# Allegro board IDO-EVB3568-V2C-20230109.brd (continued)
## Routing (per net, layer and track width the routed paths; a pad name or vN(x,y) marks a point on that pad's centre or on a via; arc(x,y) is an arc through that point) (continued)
GND_EARTH: length 49.6
  L3-POW w0.627: 17.43,78.18 J22.SH1 15.98,79.63 ; J23.SH1 36.22,78.18 ; J23.SH1 33.33,78.18 ; J23.SH1 34.78,79.63 ; 30.22,78.18 J22.SH2 ; J22.SH2 33.12,78.18 ; J22.SH2 31.67,79.63 ; 49.02,78.18 J23.SH2 50.47,79.63
  BOTTOM w0.127: HOLE1.1 4.26,74.49
  BOTTOM w1.524: J22.SH1 J22.SH2 J23.SH1 J23.SH2
GND_IN: length 33.4
  TOP w0.127: v1(9.54,65.35) 9.54,66.77 v1(9.8,67.03)
  TOP w0.508: L1.2 10.09,64.31 10.36,64.59 v1(10.36,65.35) ; L1.2 10.05,64.21 9.54,63.7 v1(8.97,63.7) ; L1.2 9.79,64.57 ; v1(8.99,67.03) v1(9.8,67.03) ; v1(9.54,65.35) 9.54,64.82 9.79,64.57 ; 9.79,64.57 v1(8.99,64.57)
  L3-POW w0.627: 3.42,22.96 J30.2 ; J30.2 4.19,22.18 ; J30.2 4.97,22.96 ; J30.2 4.19,23.73 ; J1.2 12.48,81.32 ; J1.2 11.5,79.64 ; J1.2 11.5,82.99 ; J1.2 10.52,81.32 ; 10.01,3 J18.2 10.79,3.78 ; J32.1 11.42,84 ; J32.1 10.65,83.22 ; J32.1 9.87,84 ; J32.1 10.65,84.78 ; 6.3,79.64 J1.3 ; J1.3 5.32,81.32 ; J1.3 6.3,82.99 ; J1.3 7.28,81.32 ; J32.2 8.65,84.78 ; J32.2 7.87,84 ; J32.2 9.42,84 ; J32.2 8.65,83.22 ; 4.19,24.18 J30.1 ; J30.1 4.19,25.73 ; J30.1 3.42,24.96 ; J30.1 4.97,24.96 ; 8.79,3.78 J18.1 9.57,3
  vias: v1(9.3,12.65) v1(9.47,11.76) v1(9.45,11.02) v1(9.86,73.76) v1(9.86,73.05) v1(9.86,12.4) v1(10.06,11.73) v1(10.54,73.76) v1(10.57,73.1) v1(11.18,73.74) v1(11.18,73.08) v1(13.28,8.33) v1(13.84,8.36)
VBAT_RTC: length 82.1
  TOP w0.381: D70.A 75.26,32.21 74.83,31.78 74.83,25.02 v1(77.8,22.05)
  TOP w0.508: J25.1 v1(25.87,5.4) ; v1(69.06,8.71) 69.06,9.8 71.2,11.94 v1(71.2,15.57)
  L2-GND w0.508: v1(69.06,8.71) 69.6,8.18 69.6,3.18 69.42,3 v1(69.42,2.36)
  BOTTOM w0.508: v1(69.42,2.36) 37.03,2.36 34.24,5.16 26.11,5.16 v1(25.87,5.4) ; v1(77.8,22.05) 77.67,22.05 v1(71.2,15.57)
VBAT_WL_1T1R:
  vias: v1(117.04,22.43) v1(117.42,21.92) v1(117.81,22.43) v1(121.97,35.26) v1(121.97,34.62) v1(121.97,33.99)
VBUSM: length 5.7
  TOP w0.254: R74.1 103.4,45.47 103.58,45.29 104.22,45.29 104.76,44.74 U8.35
VCC1V5_DVP: length 46.6
  TOP w0.254: J20.3 45.96,9.69 C100.2
  TOP w0.305: v1(66.62,11.38) 65.02,9.78 J19.3
  TOP w0.381: v1(66.62,11.38) C254.2 ; v1(47.35,10.26) 47.35,10.78 C100.2 ; C107.2 63.01,20.85 62.11,19.95 C108.1 R175.2
  TOP w0.508: U16.5 62.75,21.99 63.2,21.54 C107.2 64.33,20.85 C106.2 64.65,20.84 65.35,20.14 65.35,18.69 65.96,18.08 67.56,18.08 69.16,16.48 69.16,14.05 v1(68.4,13.28)
  BOTTOM w0.508: v1(47.35,10.26) 47.37,10.29 54.41,10.29 54.76,10.64 62.43,10.64 62.89,10.19 65.43,10.19 v1(66.62,11.38) 66.62,11.46 68.4,13.23 v1(68.4,13.28)
VCC1V8_DVP: length 68.7
  TOP w0.254: 43.23,16.38 43.23,15.57 Q17.1 43.24,15.5 42.85,15.11 42.85,14.09 R161.2 ; 43.23,16.38 44.65,16.38 44.83,16.21 v1(45.14,16.21) ; 43.23,16.38 41.38,16.38 41.2,16.21 41.2,15.58 Q16.1 ; v1(45.73,10.28) 45.46,10 J20.4 ; v1(47.04,16.23) 46.45,15.65 R162.2
  TOP w0.305: v1(65.61,11.38) 65.61,11 64.52,9.91 J19.4
  TOP w0.381: C104.2 46.18,10.73 v1(45.73,10.28) ; R166.2 48.74,13.94 v1(49.23,14.43) 49.23,15.85 48.32,16.76 48.31,16.76 48.25,16.82 47.76,16.82 47.17,16.23 v1(47.04,16.23) ; C255.2 v1(65.61,11.38)
  TOP w0.508: v1(67.51,15.95) 67.77,15.7 R156.2 ; U15.5 57.63,21.69 57.25,21.31 C103.2 ; C103.2 57.26,20.84 C102.2 58.81,20.84 59.23,20.42 59.23,18.9 58.88,18.54 v1(58.88,17.98) 58.37,17.48 53.95,17.48 52.07,15.6 52.07,15.16 51.32,14.41 50.76,14.41 v1(50.75,14.43) 50.75,14.17 49.1,12.52 49.1,9.09 v1(49.23,8.97) ; C103.2 56.91,20.85 56.59,20.52 56.59,20.4 56.14,19.95 R172.2
  BOTTOM w0.381: v1(50.75,14.43) v1(49.23,14.43) ; v1(47.04,16.23) 46.86,16.05 45.29,16.05 v1(45.14,16.21)
  BOTTOM w0.508: v1(49.23,8.97) 47.35,8.97 46.03,10.28 v1(45.73,10.28) ; 64.97,13.92 64.97,12.01 v1(65.61,11.38) ; 64.97,13.92 66.12,15.06 66.62,15.06 v1(67.51,15.95) ; 64.97,13.92 63.83,15.06 60.4,15.06 59.51,15.95 59.51,17.35 v1(58.88,17.98)
VCC2V8_DVP: length 36.6
  TOP w0.381: C111.2 68.27,20.72 67.42,19.87 R177.2
  TOP w0.508: C253.2 68.25,11.95 68.28,11.97 v1(68.28,12) 69.8,13.52 69.8,18.11 70.43,18.75 70.43,20.02 69.73,20.72 C110.2 68.41,20.72 C111.2 68.4,21.41 68.28,21.54 U17.5
  BOTTOM w0.508: v1(68.28,12) 65.83,9.55 62.61,9.55 62.03,8.97 55.27,8.97 54.61,9.63 v1(48.34,9.63)
VCC3V3_PHY0: length 33.7
  TOP w0.203: U19.29 36.15,35.89 35.89,35.63 35.89,35.45
  TOP w0.254: C149.2 39.57,43.07 38.87,43.07 37.82,42.01 U19.40
  TOP w0.381: C152.2 37.22,35.45 37.67,35 v1(37.67,34.75) ; C152.2 C151.2 35.89,35.45 ; C152.2 36.91,35.89 v1(36.78,36.02) ; C149.2 39.89,44.33 40.34,44.78 R211.2 v1(40.65,44.2) ; C148.2 28.09,43.51 R258.2 28.19,44.5 29.3,44.5 29.67,44.13 29.67,43.97 30.07,43.57 30.12,43.57 C150.2 ; v1(38.56,36.7) 38.7,36.56 39.72,36.56 40.15,37 R226.2 ; R230.2 44.15,36.71 v1(43.94,36.5)
  BOTTOM w0.381: v1(40.65,44.2) 41.22,44.78 45.16,44.78 45.54,44.4 45.54,40.72 45.16,40.34 45.16,38.68 44.58,38.1 44.58,37.13 v1(43.94,36.5) ; v1(38.56,36.7) 38.56,35.64 v1(37.67,34.75)
  vias: v1(30.68,42.93) v1(30.68,42.37)
VCC3V3_PHY1: length 44.5
  TOP w0.254: U20.40 62.84,41.88 63.42,42.47 63.8,42.47 64.85,43.51 64.85,43.87 ; U20.29 61.42,36.96 60.81,36.35 v1(60.81,36.02) ; U20.11 57.2,41.88 v1(56.21,42.88)
  TOP w0.381: 64.85,43.87 64.47,43.87 v1(63.56,42.96) ; R278.2 R274.2 68.09,34.09 68.43,33.76 R306.2 ; C174.2 55.78,43.31 v1(56.21,42.88)
  TOP w0.508: C173.2 64.85,44.28 64.85,43.87 ; v1(67.01,34.87) 67.01,33.67 C172.2 67.41,33.32 R306.2 ; v1(62.81,35.61) C176.1 C175.2 61.87,35.51 61.37,36.02 v1(60.81,36.02)
  BOTTOM w0.508: v1(60.81,36.02) 57.1,36.02 54.31,38.81 54.31,41.22 55.96,42.88 v1(56.21,42.88) 56.3,42.96 v1(63.56,42.96) ; v1(62.81,35.61) 63.55,34.87 v1(67.01,34.87)
VCC3V3_SD: length 114.9
  TOP w0.254: J2.210 31.92,52.05
  TOP w0.381: J3.4 105.1,74.75 103.45,73.1 D2.2 104.69,72.57 C31.2 105.3,71.96 v1(105.49,71.96) ; v1(41,45.85) 40.44,46.41 39.73,46.41 38.81,47.32 37.03,47.32 35.36,49 34.06,49 33.58,49.48 32.3,49.48 31.92,49.86 31.92,52.05
  BOTTOM w0.381: v1(105.49,71.96) 106.38,71.96 107.14,71.2 107.14,69.93 107.9,69.16 107.9,68.53 106.63,67.26 101.09,67.26 100.97,67.13 98.04,67.13 97.28,66.37 95.25,66.37 94.21,65.33 84.43,65.33 82.63,67.13 70.76,67.13 70.21,66.57 69.62,66.57 65.74,62.69 65.74,53.29 66.47,52.55 66.47,47.5 64.52,45.54 55.76,45.54 53.68,47.62 52.48,47.62 52.27,47.63 51.95,47.63 50.12,45.8 42.98,45.8 42.54,46.24 41.84,46.24 41.45,45.85 v1(41,45.85)
VCC5V0_M:
  vias: v1(21.72,63.07) v1(21.74,63.83) v1(22.35,63.07) v1(22.94,63.07) v1(23.19,63.83) v1(23.57,63.07) v1(24.21,63.07)
VCC5V0_USB1: length 1.3
  TOP w1.016: J7.1 121.72,3.89 122,4.17
  vias: v1(119.08,19.13) v1(119.84,19.13) v1(124.56,14.17) v1(124.56,13.54)
VCC5V0_USB2: length 1.6
  TOP w0.635: 109.93,3 J8.1 110.71,3.78
VCC5V0_USB3: length 1.6
  TOP w0.635: 98.91,3 J9.1 99.69,3.78
VCC5V0_USB_HOST1: length 3.7
  TOP w0.635: 90.67,77.27 J6.10 89.94,78
  BOTTOM w0.635: J6.10 90.67,77.27 ; J6.10 89.2,77.27 ; J6.10 89.94,78
  vias: v1(91.11,73.71) v1(91.59,74.09)
VCC5V0_USB_HOST2: length 1.7
  TOP w1.016: J6.1 91.54,80.47 91.59,80.42
VCC5V0_USB_OTG0: length 1.2
  TOP w0.203: R27.1 123.9,82.01 D7.2
  vias: v1(119.1,56.06) v1(119.74,55.96) v1(123.77,82.88) v1(124.36,82.88) v1(127.63,71.04) v1(128.19,70.64) v1(130.76,82.75) v1(131.39,82.75)
VCC5V_HDMI_TX: length 11
  TOP w0.305: J14.18 67.25,82.11 67.51,82.37 68.15,82.37 68.53,81.99 68.53,80.62 69.88,79.27 71.2,79.27 72.19,78.28 C85.2 72.86,78.62 72.9,78.62 73.07,78.79 D43.C
VCC5V_SPK: length 17.6
  TOP w0.508: 118.95,69.29 119.84,69.29 120.09,69.55 121.17,69.55 C249.2 C252.2 120.97,67.44 120.2,67.44 ; R86.2 109.37,69.61 C250.2 C251.2 111.14,69.29 U11.4 114,69.29 v1(114.38,68.91)
  BOTTOM w0.508: 118.77,68.91 v1(114.38,68.91)
  vias: v1(113.87,68.91) v1(120.32,67.64) v1(120.32,67.03)
VCC5V_SYS: length 55.6
  TOP w0.254: Q5.1 68.76,74.96 v1(68.76,75.06)
  TOP w0.381: C8.2 R4.2 72.85,69.39 73.13,69.67 v1(73.13,70.03) ; 73.61,75.01 D43.A 73.61,76.56 74.88,77.83 74.88,79.6 74.35,80.14 73.48,80.14 71.83,81.79 71.83,83.26 71.45,83.64 57.73,83.64 57.29,84.09 54.62,84.09 ; 73.61,75.01 D42.A 74.22,74.73 74.92,74.02 75.26,74.02 R7.2 ; 73.61,75.01 73.54,75.08 v1(73.13,75.08)
  L2-GND w0.381: v1(60.32,66.5) 61.8,65.02 65.18,65.02 68.66,68.5 71.93,68.5 73.13,69.7 v1(73.13,70.03)
  BOTTOM w0.203: v1(68.76,75.06) 69.77,75.06 70.33,75.62 72.82,75.62 73.13,75.31 v1(73.13,75.08)
  vias: v1(19.18,65.56) v1(19.45,64.96) v1(19.9,65.46) v1(20.04,64.63) v1(22.86,85.93) v1(23.34,85.45) v1(23.79,85.96) v1(24.08,85.45) v1(24.46,85.9) v1(24.71,85.37) v1(54.43,76.3) v1(54.8,75.84) v1(55.12,76.33) v1(55.48,76.9) v1(55.47,75.84) v1(58.27,66.47) v1(59,67.13) v1(59,66.5) v1(59.72,67.13) v1(59.72,66.5) v1(60.4,67.13)
VCC12V_DCIN: length 49.1
  TOP w0.635: J32.4 5.42,84 ; J32.4 4.65,84.78 ; J32.4 3.87,84 ; J32.4 4.65,83.22 ; J18.5 16.79,3.78 ; J18.5 16.79,2.22 ; J18.5 16.01,3 ; J18.5 17.57,3 ; 8.08,14.23 J29.1 ; J29.1 7.25,15.06 ; J29.1 8.91,15.06 ; 2.9,79.64 J1.4 ; J1.4 1.92,81.32 ; J1.4 2.9,82.99 ; J1.4 3.88,81.32 ; J17.1 20.46,6.81 ; J17.1 19.63,5.98 ; J17.1 19.63,7.64 ; 4.19,16.18 J30.5 3.42,16.96 ; 3.42,14.96 J30.6 ; J30.6 4.19,15.73 ; J30.6 4.97,14.96 ; J30.6 4.19,14.18 ; 5.87,84 J32.3 ; J32.3 6.65,84.78 ; J32.3 7.42,84 ; J18.6 18.79,3.78 ; J18.6 18.79,2.22 ; J18.6 19.57,3 ; J18.6 18.01,3
  TOP w2.032: F2.1 16.26,72.11 16.21,72.16
  L2-GND w0.627: J29.1 8.08,15.74 ; J29.1 7.4,15.06 ; J29.1 8.08,14.38 ; 18.79,2.22 J18.6 ; J18.6 19.57,3 ; J18.6 18.79,3.78 ; J18.6 18.01,3 ; J18.5 17.57,3 ; J18.5 16.01,3 ; J18.5 16.79,2.22 ; J18.5 16.79,3.78 ; 3.42,14.96 J30.6 ; J30.6 4.19,15.73 ; J30.6 4.19,14.18 ; J30.6 4.97,14.96 ; 19.63,6.13 J17.1 18.96,6.81 ; 4.19,16.18 J30.5 ; J30.5 3.42,16.96 ; J30.5 4.97,16.96
  BOTTOM w0.508: J32.4 2.9,82.25 J1.4
VCC_1V8: length 335.3
  TOP w0.254: R399.1 126.85,31.12 127.3,31.57 127.3,33.98
  TOP w0.381: R298.1 63.27,29.82 64.6,28.49 64.6,23.83 ; Q19.1 128.52,33.98 v1(128.75,34.21) ; J2.237 25.17,60.17
  TOP w0.508: R398.1 127.53,37.74 v1(127.84,38.05) ; 70.56,17.4 70.56,17.73 71.2,18.36 71.2,20.78 70.18,21.79 69.65,21.79 69.14,22.3 69.14,23.42 68.73,23.83 54.91,23.83 54.33,23.24 v1(54.33,22.94) ; 70.56,17.4 v1(74.12,17.4) ; 70.56,17.4 v1(70.56,16.21) ; 23.93,30.15 22.79,31.29 18.54,31.29 15.57,34.26 15.57,36.37 14.47,37.48 14.47,45.74 14.44,45.77 v1(14.44,45.99) ; 23.93,30.15 24.26,29.82 24.46,29.62 24.82,29.62 v1(24.85,29.6) ; 23.93,30.15 23.29,29.51 23.29,28.96 22.78,28.46 R408.1 ; v1(131.6,12.27) 131.93,12.27 133.27,10.92 133.27,6.91 128.07,1.7 97.59,1.7 96.9,2.39 v1(96.9,7.01) ; R413.1 90.25,15.04 v1(90.27,15.06) ; v1(49.1,16.87) 49.1,17.2 48.07,18.22 47.49,18.22 46.48,19.23 44.45,19.23 43.61,20.07 43.61,20.42 v1(43.56,20.47) ; v1(114.38,48.46) 117.04,45.8 121.31,45.8 122.17,46.66 124.94,46.66 125.81,45.8 127.86,45.8 129.01,44.65 v1(129.49,44.65) ; v1(25.35,57.68) 25.17,57.86 25.17,60.17 ; R154.2 63.17,17.29 63.28,17.39 63.82,17.39 63.93,17.29 R155.2 67.19,17.29 v1(68.28,16.21) ; R200.1 v1(96.55,26.56) ; v1(36.75,29.36) 36.34,29.77 R250.1
  L2-GND w0.508: v1(74.12,17.4) 74.65,17.4 75.16,16.89 75.16,10.62 75.74,10.03 75.74,5.49 76.2,5.03 85.73,5.03 86.64,5.94 86.64,6.58 86.62,6.6 v1(86.62,6.6)
  BOTTOM w0.483: 40.85,21.06 40.55,21.06 40.55,21.05 40.02,21.05 40.02,21.06 39.98,21.06
  BOTTOM w0.508: v1(114.38,48.46) 114.38,50.19 115.32,51.13 116.57,51.13 R30.2 ; 90.27,14.05 90.27,12.14 89.76,11.63 87.79,11.63 86.49,10.33 86.49,6.73 v1(86.62,6.6) ; 90.27,14.05 90.07,14.25 88.87,14.25 88.32,14.81 88.32,17.83 87.91,18.24 83.52,18.24 82.82,18.93 82.82,20.28 84.99,22.46 84.99,22.47 85.38,22.86 85.39,22.86 85.52,22.99 90.42,22.99 90.96,23.52 93.52,23.52 ; 90.27,14.05 v1(90.27,15.06) ; v1(54.33,22.94) 54.31,22.94 50.98,19.61 50.98,17.98 50.43,17.44 49.86,16.87 v1(49.1,16.87) ; v1(129.49,44.65) 129.49,39.7 v1(127.84,38.05) 128.75,37.13 v1(128.75,34.21) 128.75,15.98 129.34,15.39 129.34,13.94 130.71,12.57 131.29,12.57 v1(131.6,12.27) ; 40.85,21.06 42.98,21.06 v1(43.56,20.47) ; 39.98,21.06 39.24,21.79 39.24,25.86 39.47,26.09 39.47,28.22 38.66,29.03 37.08,29.03 v1(36.75,29.36) 36.4,29.01 33.97,29.01 33.04,28.08 26.99,28.08 26.96,28.12 26.9,28.12 25.37,29.64 24.91,29.64 24.87,29.6 v1(24.85,29.6) ; v1(96.55,26.56) 95.45,26.56 93.52,24.64 93.52,23.52 ; v1(14.44,45.99) 14.44,46.54 14.47,46.57 14.47,46.71 14.81,47.05 14.81,50.09 17.45,52.73 17.45,54.46 17.96,54.97 19.61,54.97 22.33,57.68 v1(25.35,57.68) ; 93.52,23.52 94.01,23.52 95.19,22.34 95.19,20.23 97.56,17.86 97.56,7.67 v1(96.9,7.01) ; v1(68.28,16.21) v1(70.56,16.21)
VCC_1V8_HUB: length 47.3
  TOP w0.254: v1(107.71,45.67) 107.76,45.62 U8.29 ; C60.2 108.28,34.11 108.26,34.13 U8.9 ; U8.3 105.26,34.27 104.72,33.73 C61.2 ; U8.26 109.26,44.87 109.52,45.14 110.66,45.14 C50.2
  TOP w0.381: v1(107.71,45.67) 107.77,45.73 C62.2 ; v1(104.09,32.66) 104.46,33.04 C61.2 ; v1(107.7,32.72) 107.9,32.92 108.16,32.92 C60.2
  TOP w0.508: v1(111.96,46.18) 111.39,45.6 C50.2 113.35,43.38 115.9,43.38 118.69,40.59 v1(118.69,37.16)
  BOTTOM w0.508: v1(107.71,45.67) 108.6,46.56 111.58,46.56 v1(111.96,46.18) ; v1(118.69,37.16) 115.82,37.16 111.38,32.72 v1(107.7,32.72) 104.14,32.72 v1(104.09,32.66)
VCC_3V3: length 46.5
  TOP w0.203: v1(24.71,56.46) 24.71,56.72 24.49,56.95 24.49,59.08 23.17,60.39 J2.245 ; R14.1 v1(30.05,22.23)
  BOTTOM w0.203: v1(30.05,22.23) 30.05,23.44 29.06,24.43 26.87,24.43 26.29,25.02 26.29,26.39 23.75,28.93 23.75,42.6 23.88,42.72 23.88,43.36 24.85,44.34 24.85,51.93 26.11,53.19 26.11,55.96 25.6,56.46 v1(24.71,56.46)
VCC_3V3_HUB: length 38.9
  TOP w0.203: R66.2 102.69,47.37 102.21,47.85 99.87,47.85 97.71,45.69 97.71,44.4 98.09,44.02 R65.1
  TOP w0.254: U8.19 113.33,39.95 ; U8.13 113.15,36.95 113.23,37.03 C57.2 ; v1(105.23,45.67) 105.33,45.67 106.26,44.74 U8.32 ; U8.27 108.76,45.19 C58.2
  TOP w0.381: v1(110.26,45.9) 110.14,45.9 C58.2 ; v1(116.31,36.27) 116.31,38.28 115.27,39.32 114.5,39.32 114.05,39.77 C59.2 113.37,39.95 113.36,39.95 113.33,39.95 ; C57.2 114.05,36.09 v1(114.88,35.26) ; R65.1 99.19,44.43 v1(99.54,44.78) ; v1(105.23,45.67) 104.85,46.05 C55.2 ; R55.2 106.56,32.14 v1(106.38,31.95) 106.19,32.14 R54.2 ; R58.2 v1(102.76,32.14)
  BOTTOM w0.508: 105.23,41.61 107.65,41.61 109.04,43 109.04,44.65 110.26,45.88 v1(110.26,45.9)
  vias: v1(100.81,40.84) v1(101.47,40.82) v1(101.55,32.08) v1(102.18,32.08)
VCC_3V8: length 3
  BOTTOM w0.508: C207.2 R343.2 C203.2 100.67,55.14 v1(100.84,54.97)
  vias: v1(95.22,49.48) v1(95.22,48.9) v1(95.86,49.48) v1(95.86,48.9) v1(98.32,63.47) v1(99.09,63.47) v1(99.85,63.47) v1(100.51,63.42) v1(101.27,63.42) v1(105.64,51.64) v1(106.27,51.64) v1(106.73,51.08) v1(106.95,51.73) v1(120.47,51.77) v1(120.85,52.4) v1(121.11,51.77)
VCC_5V: length 47.5
  TOP w0.127: v1(26.21,27.69) 26.16,27.64 C22.2
  TOP w0.203: 26.54,26.8 26.54,27.23 v1(26.59,27.28)
  TOP w0.254: 34.68,16.08 R133.1 ; 34.68,16.08 34.67,16.07 v1(34.67,15.67) ; 34.68,16.08 32.6,16.08
  TOP w0.305: v1(33.3,3.25) 32.61,3.25 32.13,3.73 32.13,7.77 32.54,8.18 32.54,9.32 33.73,10.52 33.73,10.9 34.04,11.2 34.08,11.2 v1(34.14,11.26) ; Q7.1 32.6,16.08 32.27,15.75 C94.2 32.27,14.92 31.79,14.44 U14.5
  TOP w0.381: C17.2 R11.2 23.14,26.57 v1(23.24,26.47)
  TOP w0.635: J24.35 132.04,14.17 ; J24.35 129.99,14.17 ; J24.35 131.01,13.15 ; 133.55,13.15 J24.36 132.53,14.17
  TOP w1.016: J29.3 9.64,19.06 9.65,19.08
  L2-GND w0.254: v1(12.78,23.11) 15.93,23.11 17.3,24.49 21.26,24.49 v1(23.24,26.47)
  L3-POW w0.627: J17.3 16.31,6.81 ; J17.3 15.63,7.49 ; J17.3 15.63,6.13
  BOTTOM w0.305: v1(34.14,11.26) 34.16,11.28 34.16,11.56 34.47,11.86 34.47,15.47 v1(34.67,15.67)
  BOTTOM w1.016: v1(15.98,7.95) 15.98,7.15 J17.3 15.32,7.13 v1(15.32,7.98)
  vias: v1(11.89,23.83) v1(11.89,22.94) v1(11.89,22.05) v1(11.89,21.16) v1(11.89,20.27) v1(12.78,21.72) v1(12.78,20.27) v1(24.99,28.83) v1(25.43,28.47) v1(26.24,21.74) v1(26.82,21.72) v1(33.27,2.62) v1(33.93,3.25) v1(33.93,2.59) v1(34.57,3.25) v1(34.59,2.62) v1(35.15,2.64) v1(83.74,19.81) v1(84.02,20.4) v1(91.34,7.49) v1(91.34,6.73) v1(92.1,7.49) v1(92.1,6.73) v1(92.86,7.49) v1(92.86,6.73) v1(93.65,53.01) v1(93.86,53.65) v1(94.01,3.91) v1(94.01,3.3) v1(94.28,52.45) v1(94.41,53.16) v1(94.67,3.91) v1(94.67,3.3) v1(95.3,3.91) v1(95.33,3.28) v1(96.09,17.35) v1(96.62,63.47) v1(96.72,17.35) v1(96.93,62.92) v1(97.26,63.47) v1(97.56,62.92) v1(104.85,6.4) v1(104.85,5.66) v1(105.71,64.29) v1(106.48,64.29) v1(107.24,64.29) v1(108,64.29) v1(118.85,49.1) v1(119.41,49.1) v1(119.38,48.51) v1(119.91,24.21) v1(119.96,49.1) v1(119.96,48.46) v1(119.94,23.6) v1(120.47,24.1) v1(120.5,23.5) v1(127.66,14.55) v1(127.66,13.92) v1(127.66,13.28) v1(128.3,14.55) v1(128.3,13.92) v1(128.3,13.28)
VCC_12V: length 17.8
  TOP w0.254: R3.2 72.19,67.59 73.79,69.19 73.79,70.12 v1(73.8,70.13)
  L2-GND w0.203: 71.07,69.42 71.12,69.42 72.23,70.53 72.23,70.53 72.62,70.92 73.2,70.92 73.79,70.33 73.79,70.14 v1(73.8,70.13)
  L2-GND w0.254: v1(65.86,75.49) 65.91,75.44 65.91,70.94 67.59,69.27 70.92,69.27 71.07,69.42
  vias: v1(12.36,30.43) v1(12.38,29.75) v1(13.67,60.4) v1(13.67,59.84) v1(14.3,60.4) v1(14.3,59.84) v1(14.43,29.77) v1(14.45,30.43) v1(14.94,60.4) v1(14.94,59.84) v1(56.52,76.86) v1(56.52,76.2) v1(56.59,77.44) v1(65.35,75.74) v1(65.41,75.16)
VCC_EDP_OUT: length 6.3
  TOP w1.016: 6.58,24.79 6.85,25.06 J29.6 ; J29.2 6.89,17.06 6.65,17.3 ; J29.4 6.56,21.06 6.55,21.06
  BOTTOM w0.635: 8.08,25.89 J29.6 8.91,25.06
VCC_EDP_OUT_: length 4.5
  BOTTOM w1.016: 9.22,51.82 8.41,51 J28.1 J28.2
VCC_LEDA_TX0: length 14.1
  TOP w0.508: v1(29.29,22.17) 29.29,21.92 29.54,21.67 U13.5 ; v1(24.61,20.04) 23.32,21.34 23.32,22.62 D50.C
  BOTTOM w0.508: v1(24.61,20.04) 24.61,21.06 25.45,21.89 25.45,22.66 26.62,23.83 28.78,23.83 29.29,23.32 v1(29.29,22.17)
  vias: v1(18.36,23.7) v1(18.34,22.94) v1(18.36,22.17)
VCC_LEDA_TX1: length 26.1
  TOP w0.305: J13.2 92.54,9.61 92.79,9.86 93.04,9.61 J13.1
  TOP w0.508: 92.79,9.86 93.17,9.86 93.93,10.62 93.93,12.32 94.51,12.9 94.51,17.9 C81.2 C84.2 92.68,20.18 D39.C 92.09,21.86 v1(92.02,21.92) ; v1(85.65,22.2) 85.65,22.41 85.29,22.77 85.29,23.32 84.91,23.7 U12.5
  BOTTOM w0.508: v1(92.02,21.92) 86.44,21.92 86.16,22.2 v1(85.65,22.2)
VCC_LEDK_TX0: length 21.3
  TOP w0.508: R117.1 28.29,17.06 R120.2 R119.2 22.97,17.06 21.54,18.49 18.36,18.49 17.86,19 17.86,20.52 17.22,21.16 17.22,23.7 18.11,24.59 19.15,24.59 19.66,25.1 19.66,26.11 v1(19.91,26.37)
VCC_LEDK_TX1: length 24.3
  TOP w0.305: J13.9 89.04,9.56 v1(88.77,9.83) 88.54,9.6 J13.10
  TOP w0.508: R99.1 91.09,22.97 R102.2 R101.2 94.93,22.06 95.17,21.82 95.17,12.47 v1(94.59,11.89)
  BOTTOM w0.508: v1(88.77,9.83) 92.53,9.83 v1(94.59,11.89)
VCC_LVDS_OUT: length 5
  BOTTOM w0.635: J17.2 18.46,6.81 ; J17.2 17.63,7.64 ; J17.2 17.63,5.98
  BOTTOM w1.016: 13.74,5.49 13.63,5.59 J17.4 ; 9.78,5.74 9.63,5.89 9.63,6.81
  vias: v1(23.27,10.64) v1(23.83,10.36)
VCC_LVDS_OUT_: length 9.7
  TOP w0.508: Q6.3 21.41,9.73
  TOP w0.635: J16.2 5.89,29.48 ; J16.2 5.06,28.65 ; J16.2 5.06,30.31 ; J16.1 7.99,29.48 ; J16.1 7.06,28.55 ; J16.1 6.13,29.48 ; J16.1 7.06,30.41 ; 6.23,31.48 J16.3 ; J16.3 7.06,30.65 ; J16.3 7.89,31.48
  vias: v1(10.16,31.62) v1(10.24,32.18) v1(21.03,10.36) v1(21.67,10.36)
VCCA_CODEC: length 16.9
  TOP w0.508: R85.2 121.4,65.38 C68.2 120.28,64.21 117.3,64.21 v1(116.83,64.68) ; v1(111.02,65.74) C67.2 111.46,66.88 111.59,66.75 112.03,66.75 112.03,66.75 112.85,66.75
  BOTTOM w0.508: v1(116.83,64.68) 116.43,65.07 116.43,65.41 114.88,66.95 112.24,66.95 v1(111.02,65.74)
VCCIO_PHY0: length 32.4
  TOP w0.203: U19.28 35.75,37.03
  TOP w0.254: R249.2 29.79,40.57 29.79,37.67 30.05,37.41 30.05,36.65 28.8,35.41 28.8,34.01 28.4,33.6 28.4,32.08 28.32,32 v1(28.32,31.8) ; 35.75,37.03 35.75,36.22 35,35.48 C146.2 35.26,35.19 35.32,35.19 35.53,34.98 35.53,33.19 C145.2
  TOP w0.381: R238.2 R240.2 R243.2 R246.2 R236.2 28.85,29.98 28.27,30.56 28.27,31.75 v1(28.32,31.8) ; C144.2 35.1,32.08 v1(34.82,32.36) ; C144.2 R250.2 ; C144.2 C145.2
  BOTTOM w0.381: v1(28.32,31.8) 28.47,31.95 28.55,31.95 29.18,32.59 34.59,32.59 v1(34.82,32.36)
VCCIO_PHY1: length 27.2
  TOP w0.254: R297.2 53.57,38.22 53.57,37.47 52.91,36.8 52.91,32.28 53.18,32.01 R283.2 ; C170.2 60.27,35.55 60.27,36.58 61.02,37.32 U20.28
  TOP w0.305: R285.2 61.32,33.18 61.32,34.59 60.84,35.07 C170.2
  TOP w0.381: 57.1,30.43 57.48,30.05 59,30.05 59.66,30.71 59.66,31.34 60.69,32.37 60.69,32.55 R285.2 ; 57.1,30.43 56.52,29.85 R291.2 R294.2 54.5,29.85 53.8,30.56 R283.2 ; 57.1,30.43 57.1,31.19 56.85,31.45 R288.2
VCCIO_WL: length 23.3
  TOP w0.381: R180.1 v1(105.9,28.45) ; v1(108.38,28.5) 108.38,28.97 108,29.36 R185.1
  TOP w0.508: U18.22 101.18,24.32 100.91,24.59 v1(100.66,24.59) C121.2 99.08,25.65 C120.2 C122.2 R200.2 96.82,25.25 96.82,22.4 97.56,21.67 R204.1
  BOTTOM w0.508: v1(100.66,24.59) 100.66,25.76 103.35,28.45 v1(105.9,28.45) 108.33,28.45 v1(108.38,28.5)
VDD3V3_PCIE30:
  vias: v1(44.22,20.75) v1(44.65,20.4) v1(45.16,20.78) v1(45.67,35.89) v1(45.67,35.13) v1(45.67,34.37) v1(45.67,33.6) v1(45.67,32.84) v1(45.67,32.08) v1(48.84,19.13) v1(48.84,18.49) v1(49.48,19.13) v1(49.48,18.49)
VDD10_PHY0: length 14.6
  TOP w0.203: C139.2 39.11,41.21 U19.38 ; v1(32.41,37.9) 32.44,37.9 32.47,37.86 U19.21
  TOP w0.254: U19.8 33.75,43.11 32.97,43.89 v1(32.46,43.89) ; U19.3 35.75,43.24 v1(36.4,43.89)
  TOP w0.381: C139.2 38.87,41.73 v1(38.76,41.73) ; v1(32.46,43.89) 32.21,44.15 C140.2 ; C141.2 36.73,44.22 v1(36.4,43.89)
  BOTTOM w0.508: v1(32.41,37.9) 32.39,37.92 C138.2 32.46,39.9 v1(32.46,43.89)
  vias: v1(38.18,32.21) v1(38.94,32.21) v1(39.7,32.21)
VDD10_PHY1: length 48
  TOP w0.203: v1(62.31,43.64) 61.49,43.64 61.02,43.17 U20.3 ; U20.21 58.22,37.47 57.45,36.7 56.23,36.7 C162.2 ; C165.2 58.14,44.07 58.14,43.92 59.02,43.04 U20.8
  TOP w0.254: U20.38 63.28,41.08 v1(63.47,41.28)
  TOP w0.381: C162.2 55.45,37.09 v1(55.45,36.53) ; v1(57.61,43.64) 57.61,44.3 C165.2 ; C164.1 v1(62.31,43.64)
  BOTTOM w0.508: v1(64.34,31.7) v1(63.7,31.7) 63.2,31.7 62.43,30.94 57.86,30.94 56.21,32.59 54,32.59 53.49,33.1 53.49,34.19 55.45,36.14 v1(55.45,36.53) 55.45,36.65 53.54,38.56 53.54,41.48 55.7,43.64 v1(57.61,43.64) v1(62.31,43.64) 63.85,43.64 64.23,43.26 64.23,42.59 63.91,42.27 C163.2 63.47,41.45 v1(63.47,41.28)
VDD_3V3: length 364.6
  TOP w0.203: 124.05,58.9 124.05,60.22 124.54,60.71 126.75,60.71 ; R10.1 76.25,73.89 75.82,73.46 73.2,73.46 72.97,73.69 72.97,74.32 72.44,74.85 72.44,75
  TOP w0.254: R306.1 68.44,32.4 C109.2 ; v1(97.73,42.09) 97.47,41.83 97.47,34.89 98.57,33.79 R76.1 ; R105.1 72.19,71.81 71.88,72.12 71.88,73.38 Q4.1 71.38,73.94 72.44,75 v1(72.44,75.08) 72.44,76.12 74.42,78.11 74.42,79.38 74.14,79.65 72.67,79.65 ; C79.2 73.45,14.91 R98.1 ; J28.19 8.2,67.86 8.2,57.35 9.35,56.21 14.43,56.21 ; v1(98.39,45.02) 98.83,45.47 R74.2 ; R401.1 126.57,35 v1(126.19,34.62) ; 36.34,31.06 37.03,31.06 37.67,30.43 37.67,28.52 38.56,27.64 ; R103.1 69.97,71.6 ; 69.97,71.6 69.6,71.23 69.6,70.61 68.91,69.93 68.35,69.93 68,70.28 R109.2 ; 69.97,71.6 69.65,71.92 69.65,73.76 Q3.1 70.59,74.93 v1(70.59,75.08) ; 14.68,55.96 14.68,54.05 15.44,53.29 v1(15.44,51.89) ; 14.68,55.96 14.43,56.21 ; 14.68,55.96 14.68,56.21 ; R327.2 75.34,41.17 75.52,41.36 R326.2 75.49,41.74 75.14,41.74 74.88,42 v1(74.88,42.06) ; R92.2 R93.2 v1(91.14,17.09) ; v1(127.28,30.53) 127.87,31.12 R400.1 ; R415.1 v1(89.36,15.06) ; v1(17.68,61.93) 16.33,60.58 16.33,57.86 14.68,56.21 ; R15.2 C24.2 24.65,22.7 24.89,22.46 v1(26.77,22.46) ; 14.43,56.21 14.68,56.21 ; v1(74.88,39.07) 75.12,38.82 D69.A ; R132.1 35.55,19.4 34.87,18.72 v1(34.47,18.72) ; 72.67,79.65 v1(72.67,79.17) ; 72.67,79.65 72.67,80.09 v1(71.7,81.05) ; R80.1 126.75,60.71 ; v1(110.46,79.27) 110.52,79.32 v1(110.52,81.46) ; R267.2 35.26,69.93 v1(34.87,70.31) ; C124.2 v1(125.42,32.08) ; v1(20.68,28.78) 21,28.46 R409.1
  TOP w0.508: v1(123.95,52.63) 123.95,54.03 123.24,54.74 123.24,58.56 ; v1(25.16,42) 25.16,42.02 24.69,42.49 24.69,47.57 24.21,48.05 R121.1 23.49,48.06 v1(22.05,48.06) ; 123.24,58.56 121.3,58.56 120.73,59.13 ; 123.24,58.56 123.71,58.56 124.05,58.9 ; 120.73,59.13 120.68,59.18 v1(117.63,59.18) ; 120.73,59.13 120.73,62.53 121.82,63.63 121.95,63.63 123.44,65.13 123.44,65.9 R85.1 124.1,67.75 124.1,68.78 125.09,69.77 128.73,69.77 129.46,69.04 v1(131.01,69.04) ; v1(69.27,34.37) 69.27,34.36 69.27,32.89 68.79,32.42 R306.1 ; C123.2 123.46,38.92 122.56,39.83 122.56,43.18 123.52,44.15 123.52,45.55 v1(123.65,45.67) ; R258.1 v1(26.49,44.4)
  TOP w1.016: 11.68,8.28 11.63,8.23 11.63,6.81
  L2-GND w0.254: v1(20.68,28.78) 20.37,29.08 11.18,29.08 9.7,27.61 9.7,23.52 ; 87.22,4.37 87.27,4.42 v1(87.27,6.76)
  L2-GND w0.627: J29.5 8.08,23.74 ; J29.5 8.76,23.06 ; J29.5 8.08,22.38
  L3-POW w0.627: J29.5 8.76,23.06 ; J29.5 7.4,23.06 ; J29.5 8.08,23.74
  BOTTOM w0.254: v1(22.05,48.06) 22.12,48.13 ; R112.2 v1(33.35,26.05) R111.2 ; v1(74.88,42.06) 75.39,41.55 75.39,39.57 v1(74.88,39.07) 73.99,39.07 72.49,37.57 72.49,36.65 70.82,34.98 69.88,34.98 v1(69.27,34.37) ; R384.1 17.01,62.48 17.04,62.48 17.6,61.93 v1(17.68,61.93) ; v1(72.67,79.17) 72.92,79.43 80.57,79.43 83.01,81.86 89.87,81.86 92.21,79.51 109.93,79.51 110.17,79.27 v1(110.46,79.27) ; v1(98.39,45.02) 98.39,42.75 v1(97.73,42.09) ; v1(117.63,59.18) 117.42,58.98 R37.2 ; v1(110.52,81.46) 111.1,82.04 122.66,82.04 125.76,78.94 131.6,78.94 133.86,76.68 133.86,71.88 v1(131.01,69.04) ; 25.65,43.24 25.65,43.36 ; v1(87.27,6.76) 87.27,6.76 87.27,6.87 87.18,6.97 87.18,10.13 87.77,10.72 92.25,10.72 94.11,12.57 94.11,16.59 93.6,17.09 v1(91.14,17.09) 89.81,17.09 89.36,16.64 v1(89.36,15.06) ; v1(70.59,75.08) v1(72.44,75.08) ; v1(71.7,81.05) 71.7,83.95 70.59,85.06 55.58,85.06 53.7,83.19 53.7,78.56 51.33,76.2 48.49,76.2 48.26,76.43 37.74,76.43 37.47,76.71 36.63,76.71 34.87,74.96 v1(34.87,70.31) ; v1(34.47,18.72) 34.62,18.87 34.62,21.64 34.22,22.04 34.22,22.48 34.72,22.98 v1(34.72,23.22)
  BOTTOM w0.305: J31.1 v1(28.29,19.96)
  BOTTOM w0.381: v1(26.49,44.4) 26.49,44.2 25.65,43.36
  BOTTOM w0.508: 25.65,43.24 25.65,42.49 v1(25.16,42) ; v1(123.95,52.63) 123.95,46.79 123.65,46.48 v1(123.65,45.67)
  vias: v1(12.78,13.67) v1(12.78,13.03) v1(13.41,13.41) v1(13.41,12.65) v1(17.86,48.06) v1(18.62,48.08) v1(34.72,24.97) v1(34.72,24.38) v1(34.75,23.8) v1(57.73,26.11) v1(58.37,26.11) v1(62.61,26.11) v1(63.2,26.11) v1(68.06,26.13) v1(68.66,26.44) v1(72.24,13.34) v1(72.24,12.7) v1(73,13.34) v1(73,12.7) v1(94.88,1.84) v1(95.51,1.6) v1(96.19,1.6) v1(96.85,1.45) v1(98.74,31.95) v1(99.42,31.95) v1(124.69,24.43) v1(124.92,37.16) v1(124.92,36.53) v1(124.92,35.89) v1(125.22,24.18) v1(125.55,24.82) v1(125.98,24.23)
VDD_RTC: length 5.4
  TOP w0.356: U21.8 76.77,36.64 76.28,36.14 C181.2
  TOP w0.381: D69.C 75.66,36.98 C181.2 75.66,35.4 75.26,35 D70.C
4G_PWREN_H_GPIO0_D5: length 26.8
  TOP w0.127: v1(101.55,58.04) 101.3,57.78 97.61,57.78 95.38,55.55 93.95,55.55 91.35,58.15 91.35,59.09 87.38,63.07 85.7,63.07 85.45,62.81 84,62.81 83.67,62.49 J2.11
  BOTTOM w0.127: v1(101.55,58.04) R344.1
4G_RESET_L_GPIO0_D4: length 38.2
  TOP w0.127: v1(83.9,59.89) 84.17,60.17 J2.9 ; R337.2 v1(109.68,49.1)
  BOTTOM w0.127: v1(109.68,49.1) 109.12,49.66 104.06,49.66 102.26,47.85 98.83,47.85 98.09,47.12 95.66,47.12 94.82,47.96 89.99,47.96 85.42,52.53 85.42,58.39 83.92,59.89 v1(83.9,59.89)
5G_SSRXN: length 28.7
  TOP w0.114: R423.2 87.49,66.8 87.49,66.05 88.71,64.83 88.71,63.81 89.74,62.78 94.46,62.78 94.68,62.56 94.68,60.1 96.23,58.55 102.73,58.55 103.2,59.02 106.82,59.02 107.42,59.62 107.42,60.3 107.7,60.58 J26.23
5G_SSRXP: length 28.8
  TOP w0.114: R422.2 87.73,66.78 87.73,66.15 87.92,65.96 88.08,65.96 88.33,66.22 88.5,66.22 88.66,66.05 88.66,65.89 88.41,65.64 88.41,65.48 88.95,64.93 88.95,63.91 89.84,63.02 94.56,63.02 94.92,62.66 94.92,60.2 96.33,58.79 102.63,58.79 103.1,59.26 106.72,59.26 107.18,59.72 107.18,60.23 106.9,60.51 J26.25
5G_SSTXN: length 23.2
  TOP w0.114: J26.31 104.5,60.66 104.22,60.38 104.22,60.1 103.91,59.79 102.92,59.79 102.41,59.28 96.56,59.28 95.43,60.42 95.43,62.89 94.79,63.53 90.09,63.53 89.5,64.12 89.5,66.85 C187.2
5G_SSTXP: length 22.9
  TOP w0.114: C189.2 89.74,66.81 89.74,66.53 89.85,66.41 89.88,66.41 89.99,66.3 89.99,66.07 89.88,65.96 89.85,65.96 89.74,65.84 89.74,65.61 89.85,65.5 89.88,65.5 89.99,65.39 89.99,65.16 89.88,65.04 89.85,65.04 89.74,64.93 89.74,64.22 90.19,63.77 94.89,63.77 95.67,62.99 95.67,60.52 96.66,59.52 102.31,59.52 102.82,60.03 103.81,60.03 103.98,60.2 103.98,60.39 103.7,60.67 J26.33
BT_REG_ON_H_GPIO1_D4: length 67.3
  TOP w0.127: v1(101.04,12.14) 100.2,11.3 100.2,9.89 R209.1 ; J2.18 81.92,52.33 81.68,52.09 81.68,41.67 82.5,40.84 82.5,36.02 82.63,35.89 82.63,26.49 82.83,26.29 87.63,26.29 89.39,24.54 91.61,24.54 93.21,26.14 93.21,27.28 93.62,27.69 v1(94.31,27.69)
  BOTTOM w0.127: v1(94.31,27.69) 94.31,28.22 94.79,28.7 98.17,28.7 99.31,27.57 99.31,20.61 100.91,19 100.91,12.27 v1(101.04,12.14)
BT_WAKE_HOST: length 2.6
  TOP w0.127: R199.2 113.74,18.62 112.84,19.52 U18.7
BT_WAKE_HOST_H_GPIO2_C1: length 169.7
  TOP w0.127: v1(116.28,18.62) R199.1 ; J2.228 27.42,54.19 28.02,54.79 28.02,55.7 27.64,56.08 26.62,56.08 v1(25.07,54.53)
  BOTTOM w0.127: v1(25.07,54.53) 25.07,53.19 24.31,52.43 24.31,44.56 23.33,43.58 23.33,43.01 23.21,42.89 23.21,28.7 25.7,26.2 25.7,24.05 24.71,23.06 24.71,22.3 23.8,21.39 23.8,19.28 24.84,18.24 24.84,14.94 25.48,14.3 28.22,14.3 28.93,13.59 28.93,13.14 29.42,12.65 29.42,11.81 30.05,11.19 30.05,8.59 31.06,7.57 35.13,7.57 37.57,5.13 70.79,5.13 78.05,12.4 78.05,14.94 78.44,15.32 78.44,16.97 80.98,19.51 81.12,19.51 81.33,19.51 82.12,20.29 82.12,20.57 84.29,22.75 84.29,22.76 85.09,23.55 85.1,23.55 86.21,24.66 88.95,24.66 89.3,24.31 89.51,24.31 91.75,24.31 93.52,26.09 93.52,28.52 94.23,29.24 109.09,29.24 109.55,28.78 109.62,28.78 109.65,28.75 111.33,28.75 114.76,25.32 114.76,19.38 115.52,18.62 v1(116.28,18.62)
CAM0_PDN_H_GPIO1_D0: length 52
  TOP w0.127: J2.10 83.92,52.17 82.69,50.94 82.69,42.17 83.52,41.35 83.52,36.53 83.9,36.14 83.9,35.56 84.56,34.9 84.56,34.26 83.13,32.84 83.13,27.76 83.36,27.53 v1(83.36,27.51) ; R150.1 v1(64.97,15.85)
  BOTTOM w0.127: v1(64.97,15.85) 66.09,16.97 71.58,16.97 79.96,25.35 81.48,25.35 82.5,26.37 82.5,27.13 82.88,27.51 v1(83.36,27.51)
CAM0_RST_L__GPIO1_D1: length 51
  TOP w0.127: J2.12 83.42,52.05 82.44,51.07 82.44,42.05 83.26,41.22 83.26,36.4 83.64,36.02 83.64,35.43 84.3,34.77 84.3,34.39 82.88,32.97 82.88,27.1 v1(83.13,26.85) ; R151.1 v1(65.86,15.82)
  BOTTOM w0.127: v1(65.86,15.82) 65.86,16.21 66.37,16.71 71.7,16.71 80.09,25.1 81.61,25.1 83.13,26.62 v1(83.13,26.85)
CAM1_PDN_H_GPIO1_D2: length 66.4
  TOP w0.127: R164.1 48.41,15.78 48.01,16.18 v1(48.01,16.23) ; J2.14 82.92,52.19 82.19,51.45 82.19,41.92 83.01,41.1 83.01,36.27 83.39,35.89 83.39,35 v1(83.82,34.57)
  BOTTOM w0.127: v1(48.01,16.23) 48.01,16.59 48.89,17.48 49.84,17.48 49.99,17.62 50.47,18.1 50.47,19.92 54.38,23.83 68.16,23.83 68.16,23.83 69.21,23.83 69.34,23.83 76.78,31.27 76.78,32.59 77.67,33.48 79.78,33.48 81.41,35.1 83.29,35.1 v1(83.82,34.57)
CAM1_RST_L_GPIO1_C7: length 62.2
  TOP w0.127: R165.1 50.95,16.11 v1(50.88,16.18) ; v1(83.13,34.59) 83.13,35.76 82.75,36.14 82.75,40.97 81.93,41.79 81.93,51.83 82.42,52.32 J2.16
  BOTTOM w0.127: v1(50.88,16.18) 50.88,17.22 51.46,17.81 51.46,19.38 55.65,23.57 68.06,23.57 69.32,23.57 69.32,23.57 69.47,23.57 77.04,31.14 77.04,32.46 77.8,33.22 79.91,33.22 81.28,34.59 v1(83.13,34.59)
CAM_CLKOUT0: length 2.5
  TOP w0.127: J2.108 59.42,51.98 59.46,51.94 59.46,51.39 59.39,51.31 R163.1
CAMERA_PWREN: length 21
  TOP w0.127: 59.84,28.17 56.01,28.17 55.63,27.79 55.63,27.24 R416.2 55.07,25.13 55.19,25 U15.3 ; 59.84,28.17 63.37,28.17 63.96,27.58 v1(63.96,26.09) ; 59.84,28.17 59.84,25.3 59.97,25.18 U16.3 ; U17.3 65.48,25.15 65.21,25.42 v1(65.21,26.14)
  BOTTOM w0.127: v1(63.96,26.09) 65.16,26.09 v1(65.21,26.14)
CAMERA_PWREN_GPIO4_D2: length 56.6
  TOP w0.127: J2.13 83.17,62.24 82.88,62.53 80.67,62.53 v1(80.44,62.76) ; v1(61.29,32.16) 60.15,31.01 60.15,30.56 58.88,29.29 55.58,29.29 55.07,28.78 R416.1
  BOTTOM w0.127: v1(61.29,32.16) 62.26,32.16 63.07,32.97 67.39,32.97 67.79,33.38 67.79,35.13 69.01,36.35 70,36.35 70.69,37.03 70.69,37.95 72.97,40.23 72.97,49.35 74.88,51.26 74.88,52.27 75.9,53.29 75.9,58.14 77.01,59.26 77.01,59.79 76.78,60.02 76.78,60.73 79.27,63.22 79.98,63.22 v1(80.44,62.76)
CAN1_RX: length 8.4
  TOP w0.127: J24.18 132.41,35.89 130.51,35.89 129.74,36.65 129.74,37.92 128.89,38.77 R310.5
CAN1_RX_M0: length 111.8
  TOP w0.127: R310.4 126.03,38.77 124.28,40.52 v1(124.28,41.07) ; v1(50.98,29.08) 50.88,29.18 50.88,30.28 50.39,30.76 50.39,36.53 49.25,37.67 49.25,46.2 46.69,48.77 46.69,51.64 45.92,52.4 J2.154
  BOTTOM w0.127: v1(124.28,41.07) 124.05,40.84 117.42,40.84 116.92,41.35 114,41.35 108.92,36.27 100.66,36.27 100.28,35.89 97.01,35.89 94.21,38.68 78.31,38.68 67.51,27.89 52.17,27.89 v1(50.98,29.08)
CAN1_TX: length 4.4
  TOP w0.127: J24.17 128.72,39.32 R310.6
CAN1_TX_M0: length 112.1
  TOP w0.127: v1(50.98,28.4) 50.5,28.88 50.5,30.23 50.09,30.63 50.09,36.4 49.02,37.47 49,37.47 49,46.08 46.43,48.64 46.43,51.38 45.42,52.39 J2.156 ; R310.3 126.06,39.32 124.92,40.46 v1(124.92,40.82)
  BOTTOM w0.127: v1(124.92,40.82) 124.71,40.82 124.49,40.59 117.3,40.59 116.79,41.1 114.12,41.1 109.04,36.02 100.79,36.02 100.41,35.64 96.9,35.64 94.11,38.43 78.44,38.43 67.64,27.64 51.74,27.64 v1(50.98,28.4)
CAN2_RX: length 7.5
  TOP w0.127: R401.2 128.1,35.45 D90.C 129.67,36.14 130.25,35.56 132.49,35.56 J24.20
CAN2_RX_M0: length 70.3
  TOP w0.127: J2.44 75.42,52.44 75.95,51.91 76.23,51.91 76.64,51.5 77.13,51.5 v1(77.32,51.31) ; v1(124.26,45.34) 124.26,42.7 123.82,42.26 123.82,40.88 123.98,40.72 123.98,40.26 126.63,37.61 R398.2 126.63,36.84 126.3,36.51 D90.A
  BOTTOM w0.127: v1(77.32,51.31) 78.13,51.31 79.07,50.37 79.07,49.35 78.82,49.1 78.82,46.81 82.88,42.75 96.09,42.75 97.87,40.97 99.9,40.97 100.53,40.34 102.58,40.34 102.58,40.34 103.96,40.34 104.72,41.1 107.77,41.1 112.09,45.42 119.84,45.42 119.84,45.42 122.48,45.42 122.57,45.5 122.98,45.5 123.55,44.93 123.85,44.93 v1(124.26,45.34)
CAN2_TX: length 4.8
  TOP w0.127: J24.19 130,33.48 Q19.3 128.13,32.88 127.97,32.72 R400.2
CAN2_TX_M0: length 79.4
  TOP w0.127: v1(122.76,45.03) 122.73,45.01 122.73,44.6 121.87,43.74 121.87,41.1 121.11,40.34 121.11,36.14 120.27,35.31 120.27,33.05 121.11,32.21 124.41,32.21 124.92,31.7 125.14,31.7 125.23,31.61 125.7,31.61 126.1,32.02 R399.2 126.53,32.04 Q19.2 ; v1(76.56,51.03) 76.56,51.21 76.12,51.64 75.77,51.64 74.92,52.48 J2.46
  BOTTOM w0.127: v1(76.56,51.03) 76.76,50.83 78.11,50.83 78.82,50.11 78.82,49.48 78.56,49.23 78.56,46.69 82.75,42.49 95.96,42.49 97.74,40.72 99.77,40.72 100.41,40.08 102.47,40.08 104.09,40.08 104.85,40.84 107.9,40.84 111.77,44.71 112.22,45.16 121.07,45.16 122.63,45.16 v1(122.76,45.03)
CIF_CLK0: length 56.3
  TOP w0.127: v1(80.04,26.59) 80.44,26.59 80.85,27 80.85,27.64 81.36,28.14 81.36,35.26 81.23,35.38 81.23,40.21 77.42,44.02 77.42,45.42 77.04,45.8 77.04,48.83 C95.2 75.64,49.38 R149.2 ; v1(62.18,16.03) 62.43,15.77 62.43,13.41 62.32,13.3 D102.5 D102.6 62.32,10.13 62.02,9.83 J19.9
  BOTTOM w0.127: v1(80.04,26.59) 79.68,26.59 71.07,17.98 64.14,17.98 v1(62.18,16.03)
CIF_CLK1: length 60.3
  TOP w0.127: v1(52.95,17.41) 52.91,17.45 52.91,18.24 53.04,18.36 53.04,30.81 52.27,31.57 52.27,38.03 52.29,38.05 52.29,38.07 53.54,39.32 53.54,41.73 54.2,42.39 54.2,42.77 54.2,42.77 54.2,43.81 54.84,44.45 54.84,46.24 54.2,46.88 54.2,48.21 56.39,50.4 57.18,50.4 C97.2 57.73,49.84 58.42,49.84 R421.2 58.57,49.84 59.31,49.84 R163.2 ; v1(41.3,14.17) 41.35,14.12 41.35,13.79 42.76,12.38 D103.5 D103.6 42.76,9.99 42.96,9.8 J20.9
  BOTTOM w0.127: v1(52.95,17.41) 53.04,17.32 53.04,16.92 52.65,16.54 52.65,14.27 52.04,13.67 41.61,13.67 41.35,13.92 41.35,14.12 v1(41.3,14.17)
CIF_CLKOUT_SOC: length 4.5
  TOP w0.127: R149.1 74.56,50.18 73.42,51.32 J2.52
CIF_PDN0: length 6.2
  TOP w0.127: J19.6 63.52,9.8 64.32,10.6 D102.10 D102.1 64.32,13.71 R150.2
CIF_PDN1: length 8.8
  TOP w0.127: R164.2 46.87,14.94 45.67,14.94 45.42,14.68 45.42,14.3 45.42,14.29 45.42,12.68 45.42,12.68 45.42,12.62 44.76,11.97 D103.1 D103.10 44.76,9.84 44.46,9.53 J20.6
CIF_RST0: length 8.3
  TOP w0.127: R156.1 C96.2 R151.2 64.72,13.22 64.72,10.62 64.02,9.92 J19.5
CIF_RST1: length 10.6
  TOP w0.127: J20.5 44.96,9.6 45.14,9.78 45.14,11.73 45.92,12.52 C99.2 R166.1 48.85,13.04 50.05,14.23 R165.2
CLK_32K_OUT: length 3
  TOP w0.127: v1(48.69,20.32) 49.28,20.9 R352.2
  BOTTOM w0.127: J27.68 48.13,19.75 v1(48.69,20.32)
CLK_32K_OUT_GPIO0_B0: length 37
  TOP w0.127: R352.1 52.53,22.36 52.53,30.56 51.77,31.32 51.77,38.3 53.04,39.57 53.04,41.94 53.69,42.6 53.69,42.98 53.7,42.98 53.7,44.04 53.7,44.05 53.7,44.08 54.33,44.7 54.33,46.03 53.7,46.67 53.7,48.44 56.44,51.18 57.28,51.18 58.42,52.33 J2.112
DM1_: length 16.5
  TOP w0.114: J7.2 124.6,3.87 124.6,9.98 125.56,10.95 125.56,15.66 D18.2 125.56,16.7 125.56,16.83 125.43,16.96 125.43,17.21 125.15,17.49 L8.3 125.15,17.93 R52.2
DM2_: length 8
  TOP w0.114: J8.2 113.47,3 113.59,3.11 113.59,7.57 113.23,7.92 D23.2 113.08,8.09 113.2,8.2 113.37,8.2 113.63,8.47 113.63,8.57 113.34,8.86 L9.3 113.34,9.3 R64.2
DM3_: length 8.1
  TOP w0.114: J9.2 102.46,3 102.57,3.11 102.57,5 102.96,5.38 102.96,7.27 D25.2 102.44,7.82 103.24,8.62 103.24,8.8 103.1,8.94 103.07,8.94 103.05,8.96 L10.3 102.99,8.98 102.95,9.02 R75.2
DM4: length 2.6
  TOP w0.114: J26.36 102.5,52.06 102.22,51.78 102.22,51.32 R340.1
DM_1: length 13.9
  TOP w0.114: R307.2 125.43,21.94 125.43,22.17 125.69,22.43 127.58,22.43 128.09,22.93 D65.1 128.6,22.43 128.98,22.43 129.36,22.05 129.36,18.49 129.76,18.1 131.8,18.1 132.16,18.46 132.16,19.14 132.05,19.25 J24.31
DP1_: length 16.4
  TOP w0.114: J7.3 124.84,3.88 124.84,9.88 125.81,10.85 125.81,15.67 D20.2 125.81,16.69 125.81,16.93 125.67,17.06 125.67,17.21 125.95,17.49 L8.4 125.95,17.93 R56.2
DP2_: length 8
  TOP w0.114: R67.2 114.14,9.3 L9.4 114.14,8.86 113.87,8.59 113.87,8.43 114.09,8.2 114.26,8.2 114.38,8.09 D22.2 114.18,7.92 113.83,7.57 113.83,3.11 113.94,3 J8.3
DP3_: length 8
  TOP w0.114: J9.3 102.93,3 102.81,3.11 102.81,4.9 103.2,5.28 103.2,7.26 D26.2 103.48,8.05 103.48,8.86 103.59,8.98 L10.4 103.85,9.27 R78.2
DP4: length 2.6
  TOP w0.114: J26.38 101.7,52.06 101.98,51.78 101.98,51.32 R341.1
DP_1: length 13.9
  TOP w0.114: J24.32 132.52,19.25 132.4,19.14 132.4,18.36 131.9,17.86 129.66,17.86 129.12,18.39 129.12,21.95 128.88,22.19 128.61,22.19 D64.1 128.09,21.68 127.58,22.19 125.79,22.19 125.67,22.07 125.67,21.94 R308.2
EDP_EN_H_GPIO0_C5: length 46.7
  TOP w0.127: v1(39.07,55.98) 38.91,55.83 32.59,55.83 v1(32.08,56.34) ; v1(50.77,55.19) 50.77,55.45 51,55.68 51.87,55.68 51.99,55.55 51.99,55.09 52.76,54.33 53.64,54.33 53.92,54.05 J2.130
  BOTTOM w0.127: v1(39.07,55.98) 39.62,55.42 50.55,55.42 v1(50.77,55.19) ; v1(32.08,56.34) 31.32,56.34 30.18,57.48 27.64,57.48 27.36,57.2 22.66,57.2 21.79,56.34 21.79,55.32 22.27,54.85 22.27,54.09 22.53,53.82 22.53,48.9 22.31,48.67 21.18,48.67 20.8,49.05 20.8,49.16 20.07,49.89 R393.2
EDP_ON_: length 22
  TOP w0.127: Q11.2 13.36,15.2 R388.2 13.03,14.68 v1(13.41,14.3) 13.54,14.17 R389.2
  BOTTOM w0.127: J30.4 4.19,18.93 3.38,18.11 3.38,14.55 3.89,14.05 10.11,14.05 12.65,11.51 13.67,11.51 13.89,11.73 13.89,13.82 v1(13.41,14.3)
EDP_ON_GPIO0_C3: length 80.1
  TOP w0.127: R387.2 R389.1 15,14.57 15.61,15.18 Q11.3 16.71,15.7 16.84,15.57 16.84,13.28 18.62,11.51 21.79,11.51 24.33,14.05 26.57,14.05 27.97,15.44 29.79,15.44 31.32,16.97 31.32,17.87 31.32,17.87 31.32,18.3 31.32,18.34 33.02,20.04 34.07,20.04 34.28,20.04 35.24,21 36.11,21 37.52,22.4 38.94,22.4 39.73,23.19 40.13,23.19 41.76,21.56 43.4,21.56 43.64,21.79 46.94,21.79 48.46,23.32 48.46,24.91 50.93,27.38 51.51,27.38 52.02,27.89 52.02,30.3 51.26,31.06 51.26,38.56 52.53,39.83 52.53,42.16 53.03,42.66 53.03,43.13 52.06,44.1 52.06,45.94 52.17,46.05 52.17,49.1 54.92,51.85 J2.126
EDP_PWM7: length 82.6
  TOP w0.127: J2.132 53.42,51.07 51.66,49.31 51.66,46.26 51.55,46.15 51.55,43.89 52.1,43.35 52.1,39.78 51,38.68 51,30.94 51.77,30.18 51.77,28.02 51.38,27.64 50.83,27.64 48.21,25.02 48.21,23.44 46.81,22.05 43.51,22.05 43.27,21.81 41.87,21.81 40.23,23.44 39.6,23.44 38.81,22.66 37.36,22.66 36,21.29 35.17,21.29 34.17,20.29 32.89,20.29 31.04,18.44 31.04,17.12 29.67,15.75 27.89,15.75 26.44,14.3 24.21,14.3 21.72,11.81 18.8,11.81 17.17,13.44 17.17,16.74 16.56,17.35 R390.1 15.39,16.59 13.16,16.59 12.78,16.97 12.78,17.6 12.4,17.98 U25.2
EDP_PWM7_: length 27
  TOP w0.127: R390.2 14.49,17.35 v1(14.48,17.33) U25.4
  BOTTOM w0.127: J30.3 3.12,19.89 3.12,14.43 3.76,13.79 9.98,13.79 12.52,11.25 13.79,11.25 14.17,11.63 14.17,17.03 v1(14.48,17.33)
EDP_TX_AUXN: length 24.9
  TOP w0.102: J2.197 35.17,62.24 35.05,62.36 35.05,62.9 34.48,63.46 33.67,63.46 33.38,63.17 33.38,62.94 v1(33.17,62.74)
  L3-POW w0.097: v1(33.17,62.74) 33.37,62.93 33.37,63.05 33.27,63.15 26.13,63.15 24.91,61.93 20.3,61.93 19.99,62.24 19.99,63 19.89,63.1 19.5,63.1 19.4,63 19.4,62.28 19.04,61.93 18.54,61.93 18.22,62.25 18.22,63.37 18.05,63.53 17.87,63.53 v1(17.67,63.33)
  BOTTOM w0.102: C235.2 16.99,63.27 17.26,63.55 17.45,63.55 v1(17.67,63.33)
EDP_TX_AUXN_: length 14.5
  BOTTOM w0.102: R384.2 16.01,62.74 15.98,62.77 C235.1 15.98,63.32 15.75,63.55 15.17,63.55 15.04,63.42 D77.7 D77.4 13.12,63.42 13,63.54 12.12,63.54 11.79,63.88 11.79,64.99 10.92,65.86 10.29,65.86 10.11,66.04 9.8,66.04 9.62,65.86 8.97,65.86 8.79,66.04 8.48,66.04 8.3,65.86 6.27,65.86 6.17,65.75 6.17,65.2 6.4,64.97 7.03,64.97 J28.15
EDP_TX_AUXP: length 24.6
  TOP w0.102: J2.199 34.67,62.23 34.79,62.35 34.79,62.79 34.37,63.21 33.78,63.21 33.63,63.06 33.63,62.97 v1(33.86,62.74)
  L3-POW w0.097: v1(17.65,64.03) 17.85,63.83 18.18,63.83 18.52,63.49 18.52,62.37 18.66,62.22 18.92,62.22 19.1,62.41 19.1,63.13 19.37,63.4 20.02,63.4 20.29,63.13 20.29,62.36 20.42,62.22 24.79,62.22 26.01,63.45 33.39,63.45 33.67,63.18 33.67,62.93 v1(33.86,62.74)
  BOTTOM w0.102: C236.2 16.88,64.16 17.24,63.8 17.42,63.8 v1(17.65,64.03)
EDP_TX_AUXP_: length 14.7
  BOTTOM w0.102: J28.16 5.62,65 5.92,65.3 5.92,65.86 6.17,66.11 8.19,66.11 8.38,66.29 8.89,66.29 9.08,66.11 9.52,66.11 9.7,66.29 10.21,66.29 10.4,66.11 11.03,66.11 12.04,65.1 12.04,63.98 12.23,63.79 13,63.79 13.12,63.92 D77.5 D77.6 15.24,63.92 15.51,64.19 C236.1 R385.1
EDP_TX_D0N: length 20.3
  TOP w0.102: v1(31.27,59.34) 31.05,59.56 31.05,60.51 31.17,60.64 J2.213
  L3-POW w0.097: v1(31.27,59.34) 31.07,59.54 31.07,59.84 30.8,60.12 27.18,60.12 26.07,59 22.3,59 21.46,58.16 20.77,58.16 20.68,58.26 20.68,58.41 v1(20.84,58.58)
  BOTTOM w0.102: C241.2 17.13,56.6 17.41,56.6 17.9,56.11 19.23,56.11 20.6,57.48 20.6,58.34 v1(20.84,58.58)
EDP_TX_D0N_: length 20.1
  BOTTOM w0.102: J28.7 6.83,56.77 6.38,56.77 6.22,56.92 6.22,57.78 6.32,57.89 7.95,57.89 8.98,56.86 10.12,56.86 10.22,56.76 10.22,56.41 9.85,56.03 8.53,56.03 8.28,55.78 8.28,55.09 8.56,54.81 10.34,54.81 11.56,56.03 11.56,57.38 11.71,57.53 12.55,57.53 12.65,57.43 12.65,57.12 12.92,56.86 13.35,56.86 13.47,56.73 D76.1 D76.10 14.85,56.73 14.97,56.86 15.2,56.86 15.36,56.69 15.67,56.69 15.98,56.39 C241.1
EDP_TX_D0P: length 20
  TOP w0.102: J2.215 30.67,60.67 30.8,60.54 30.8,60.23 30.8,59.56 v1(30.58,59.34)
  L3-POW w0.097: v1(30.58,59.34) 30.77,59.54 30.77,59.72 30.68,59.82 27.3,59.82 26.19,58.7 22.43,58.7 21.58,57.86 20.65,57.86 20.38,58.13 20.38,58.36 v1(20.14,58.6)
  BOTTOM w0.102: C242.2 17.33,56.86 17.51,56.86 18.01,56.36 19.12,56.36 20.35,57.59 20.35,58.39 v1(20.14,58.6)
EDP_TX_D0P_: length 20.1
  BOTTOM w0.102: J28.8 5.8,57 5.97,57.18 5.97,57.89 6.22,58.14 8.05,58.14 9.08,57.11 10.23,57.11 10.48,56.86 10.48,56.3 9.96,55.78 8.64,55.78 8.53,55.68 8.53,55.19 8.66,55.07 10.24,55.07 11.3,56.13 11.3,57.48 11.6,57.78 12.65,57.78 12.9,57.53 12.9,57.23 13.02,57.11 13.35,57.11 13.47,57.23 D76.2 D76.9 14.85,57.23 14.97,57.11 15.3,57.11 15.47,57.28 C242.1
EDP_TX_D1N: length 19.5
  TOP w0.102: v1(32.27,60.16) 32.05,60.38 32.05,60.57 32.17,60.7 J2.209
  L3-POW w0.097: v1(18.75,58.52) 18.94,58.71 18.94,59.07 19.25,59.39 19.97,59.39 20.4,59.81 25.73,59.81 26.88,60.96 31.7,60.96 32.05,60.6 32.05,60.37 v1(32.27,60.16)
  BOTTOM w0.102: v1(18.75,58.52) 18.95,58.72 18.95,58.93 18.85,59.03 17.91,59.03 17.5,58.62 17.29,58.62 C239.2
EDP_TX_D1N_: length 19.9
  BOTTOM w0.102: J28.9 6.22,59 6.1,59.13 6.1,59.72 6.27,59.89 8.61,59.89 9.7,58.8 9.7,58.27 9.96,58.01 10.75,58.01 11,58.26 11,60.3 10.75,60.55 10.75,60.71 11,60.96 11.38,60.96 11.68,60.65 11.68,60.17 11.93,59.92 12.45,59.92 12.55,59.82 12.55,59.54 12.44,59.44 11.81,59.44 11.53,59.16 11.53,58.62 11.8,58.36 13.1,58.36 13.22,58.23 D76.4 D76.7 14.9,58.23 15.02,58.36 15.18,58.36 15.45,58.62 15.63,58.62 C239.1
EDP_TX_D1P: length 18.9
  TOP w0.102: v1(31.58,60.16) 31.8,60.38 31.8,60.56 31.67,60.68 J2.211
  L3-POW w0.097: v1(31.58,60.16) 31.76,60.33 31.76,60.48 31.58,60.66 27.01,60.66 25.86,59.51 20.52,59.51 20.1,59.09 19.38,59.09 19.24,58.95 19.24,58.71 v1(19.43,58.52)
  BOTTOM w0.102: C240.2 17.14,58.9 17.42,58.9 17.8,59.28 18.95,59.28 19.2,59.03 19.2,58.75 v1(19.43,58.52)
EDP_TX_D1P_: length 20.7
  BOTTOM w0.102: J28.10 5.54,58.53 5.77,58.53 5.84,58.6 5.84,59.82 6.17,60.15 8.71,60.15 9.96,58.9 9.96,58.37 10.06,58.27 10.64,58.27 10.74,58.37 10.74,60.19 10.49,60.44 10.49,60.81 10.89,61.21 11.48,61.21 11.94,60.76 11.94,60.27 12.04,60.17 12.55,60.17 12.8,59.92 12.8,59.44 12.55,59.18 11.92,59.18 11.79,59.05 11.79,58.73 11.9,58.61 13.1,58.61 13.22,58.73 D76.5 D76.6 15.2,58.73 15.34,58.88 15.67,58.88 15.93,59.13 C240.1
EDP_TX_D2N: length 23.8
  TOP w0.102: J2.205 33.17,60.71 33.05,60.58 33.05,58.91 v1(33.27,58.69)
  L3-POW w0.097: v1(33.27,58.69) 33.07,58.89 33.07,60.71 32.01,61.77 26.59,61.77 25.43,60.6 18.94,60.6 18.59,60.26 18.59,60.05 v1(18.38,59.84)
  BOTTOM w0.102: v1(18.38,59.84) 18.38,59.91 18.54,60.07 18.54,60.6 18.26,60.88 17.24,60.88 C237.2
EDP_TX_D2N_: length 16.1
  BOTTOM w0.102: C237.1 16,60.55 15.72,60.83 15.47,60.83 15.19,61.11 15.19,61.92 15.07,62.04 14.95,62.04 14.82,61.92 D77.10 D77.1 13.34,61.92 13.23,62.03 12.91,62.03 12.58,61.7 11.23,61.7 10.67,62.26 10.67,62.73 10.23,63.17 9.76,63.17 9.4,62.81 9.4,61.41 9.15,61.16 8.43,61.16 7.7,61.9 6.3,61.9 6.12,61.72 6.12,60.93 6.37,60.68 6.74,60.68 J28.11
EDP_TX_D2P: length 23.2
  TOP w0.102: v1(32.57,58.69) 32.79,58.91 32.79,60.58 32.67,60.7 J2.207
  L3-POW w0.097: v1(19.08,59.84) 18.89,60.03 18.89,60.13 19.07,60.3 25.55,60.3 26.71,61.47 31.88,61.47 32.77,60.58 32.77,58.89 v1(32.57,58.69)
  BOTTOM w0.102: C238.2 17.16,61.16 18.34,61.16 18.87,60.63 18.87,60.05 v1(19.08,59.84)
EDP_TX_D2P_: length 16.6
  BOTTOM w0.102: J28.12 5.53,60.53 5.8,60.53 5.87,60.6 5.87,61.83 6.19,62.15 7.8,62.15 8.54,61.42 9.04,61.42 9.14,61.52 9.14,62.92 9.65,63.42 10.13,63.42 10.34,63.42 10.92,62.84 10.92,62.36 11.33,61.95 12.47,61.95 12.8,62.28 13.26,62.28 13.39,62.42 D77.2 D77.9 14.85,62.42 14.97,62.29 15.18,62.29 15.44,62.03 15.44,61.29 15.6,61.14 15.73,61.14 C238.1
EDP_TX_D3N: length 27.2
  TOP w0.102: J2.201 34.17,60.69 34.05,60.57 34.05,60.37 v1(34.27,60.15)
  L3-POW w0.097: v1(34.27,60.15) 34.06,60.36 34.06,60.83 32.28,62.61 26.29,62.61 25.06,61.39 17.55,61.39 17.04,61.9 17.04,66.27 17.24,66.48 17.47,66.48 v1(17.77,66.18)
  BOTTOM w0.102: C233.2 16.93,66.17 16.96,66.17 17.29,66.5 17.45,66.5 v1(17.77,66.18)
EDP_TX_D3N_: length 13.2
  BOTTOM w0.102: C233.1 15.76,66.45 15.09,66.45 14.78,66.14 D80.1 14.61,66.14 14.3,66.45 11.53,66.45 10.12,67.86 6.15,67.86 5.99,67.7 5.99,66.88 6.22,66.65 6.71,66.65 J28.17
EDP_TX_D3P: length 27.7
  TOP w0.102: v1(33.58,60.15) 33.8,60.37 33.8,60.56 33.67,60.69 J2.203
  L3-POW w0.097: v1(33.58,60.15) 33.76,60.33 33.76,60.71 32.16,62.31 26.41,62.31 25.19,61.09 17.42,61.09 16.74,61.77 16.74,66.4 17.12,66.78 17.48,66.78 v1(17.77,67.07)
  BOTTOM w0.102: C234.2 16.91,66.98 16.93,66.95 17.09,66.95 17.29,66.75 17.45,66.75 v1(17.77,67.07)
EDP_TX_D3P_: length 12.9
  BOTTOM w0.102: C234.1 16.01,66.99 15.72,66.7 15.12,66.7 D79.1 14.68,67.13 14.25,66.7 11.63,66.7 10.22,68.11 6.04,68.11 5.74,67.81 5.74,67.26 5.49,67.01 5.06,67.01 J28.18
EXT_EN: length 39.7
  TOP w0.127: R13.1 21.76,25.2 20.8,25.2 v1(20.65,25.35) ; J2.249 22.17,55.86 22.3,55.73 v1(22.3,55.7)
  BOTTOM w0.127: v1(22.3,55.7) 22.3,55.24 22.52,55.02 22.52,54.82 22.52,54.19 22.78,53.93 22.78,45.26 21.92,44.4 21.46,44.4 20.98,43.92 20.98,43.43 21.41,43 21.41,41.82 21.41,26.11 v1(20.65,25.35)
FE1_1_DM0: length 2.8
  TOP w0.114: R71.1 106.43,45.9 106.43,45.76 106.64,45.54 106.78,45.54 107.11,45.21 107.11,44.83 107.26,44.68 U8.30
FE1_1_DM1: length 33.5
  TOP w0.114: U8.23 112.29,41.95 112.42,42.08 115.68,42.08 117.74,40.02 117.74,31.55 118.58,30.71 118.58,29.84 v1(118.28,29.54) ; R307.1 125.2,20.61 v1(125.2,20.12) 125.43,19.89 125.43,19.89 125.43,19.77 125.15,19.49 L8.2 125.15,19.05 R52.1
  BOTTOM w0.114: v1(125.2,20.12) 125.43,20.35 125.43,20.51 125.43,20.52 125.43,21.96 124.06,23.33 122.91,23.33 118.58,27.66 118.58,29.24 v1(118.28,29.54)
FE1_1_DM2: length 45.7
  TOP w0.114: R64.1 113.34,10.41 L9.2 113.34,10.85 113.62,11.13 113.62,11.54 v1(113.4,11.76) ; v1(112.47,25.39) 112.77,25.1 113,25.1 113.27,25.36 113.27,28.01 114.28,29.02 116.31,29.02 117.01,29.72 117.01,38.89 114.91,40.98 113.21,40.98 112.79,40.56 112.19,40.56 112.08,40.45 U8.20
  BOTTOM w0.114: v1(113.4,11.76) 113.62,11.99 113.62,12.17 113.46,12.34 111.55,12.34 109.05,14.84 109.05,20.78 108.92,20.92 108.92,21.16 109.05,21.3 109.05,21.54 108.92,21.68 108.92,21.92 109.05,22.06 109.05,22.3 108.92,22.44 108.92,22.68 109.05,22.82 109.05,23.06 108.92,23.2 108.92,23.44 109.05,23.58 109.05,24.22 109.92,25.08 112.16,25.08 v1(112.47,25.39)
FE1_1_DM3: length 41.6
  TOP w0.114: v1(111.65,26.65) 111.95,26.35 112.09,26.35 112.28,26.54 112.28,28.08 114,29.79 115.9,29.79 116.15,30.05 116.15,34.94 115.43,35.66 115.43,37.5 114.5,38.43 113.28,38.43 112.62,39.09 112.24,39.09 112.1,38.95 U8.17 ; R75.1 103.05,10.39 L10.2 103.05,10.73 103.24,10.92 103.24,11.23 v1(102.71,11.76)
  BOTTOM w0.114: v1(111.65,26.65) 111.35,26.35 109.57,26.35 107.52,24.29 107.52,23.95 107.39,23.83 107.39,23.57 107.52,23.44 107.52,23.19 107.39,23.06 107.39,22.81 107.52,22.68 107.52,22.43 107.39,22.3 107.39,22.05 107.52,21.92 107.52,21.67 107.39,21.54 107.39,21.29 107.52,21.16 107.52,17.18 102.95,12.62 102.95,12.01 v1(102.71,11.76)
FE1_1_DM4: length 22.7
  TOP w0.114: R340.2 102.22,49.67 102.22,49.53 102.55,49.2 104.06,49.2 104.34,48.92 104.34,48.66 v1(104.63,48.38) ; v1(106.42,42.65) 106.67,42.41 106.67,39.41 108.5,37.58 110.4,37.58 110.53,37.45 U8.14
  BOTTOM w0.114: v1(106.42,42.65) 106.63,42.86 106.63,43.38 106.5,43.51 106.5,43.76 106.63,43.89 106.63,44.15 106.5,44.27 106.5,44.53 106.63,44.65 106.63,44.91 106.5,45.03 106.5,45.29 106.63,45.42 106.63,45.67 106.5,45.8 106.5,46.05 106.63,46.18 106.63,46.56 107.26,47.19 107.26,48.46 106.82,48.91 104.47,48.91 104.33,48.77 104.33,48.68 v1(104.63,48.38)
